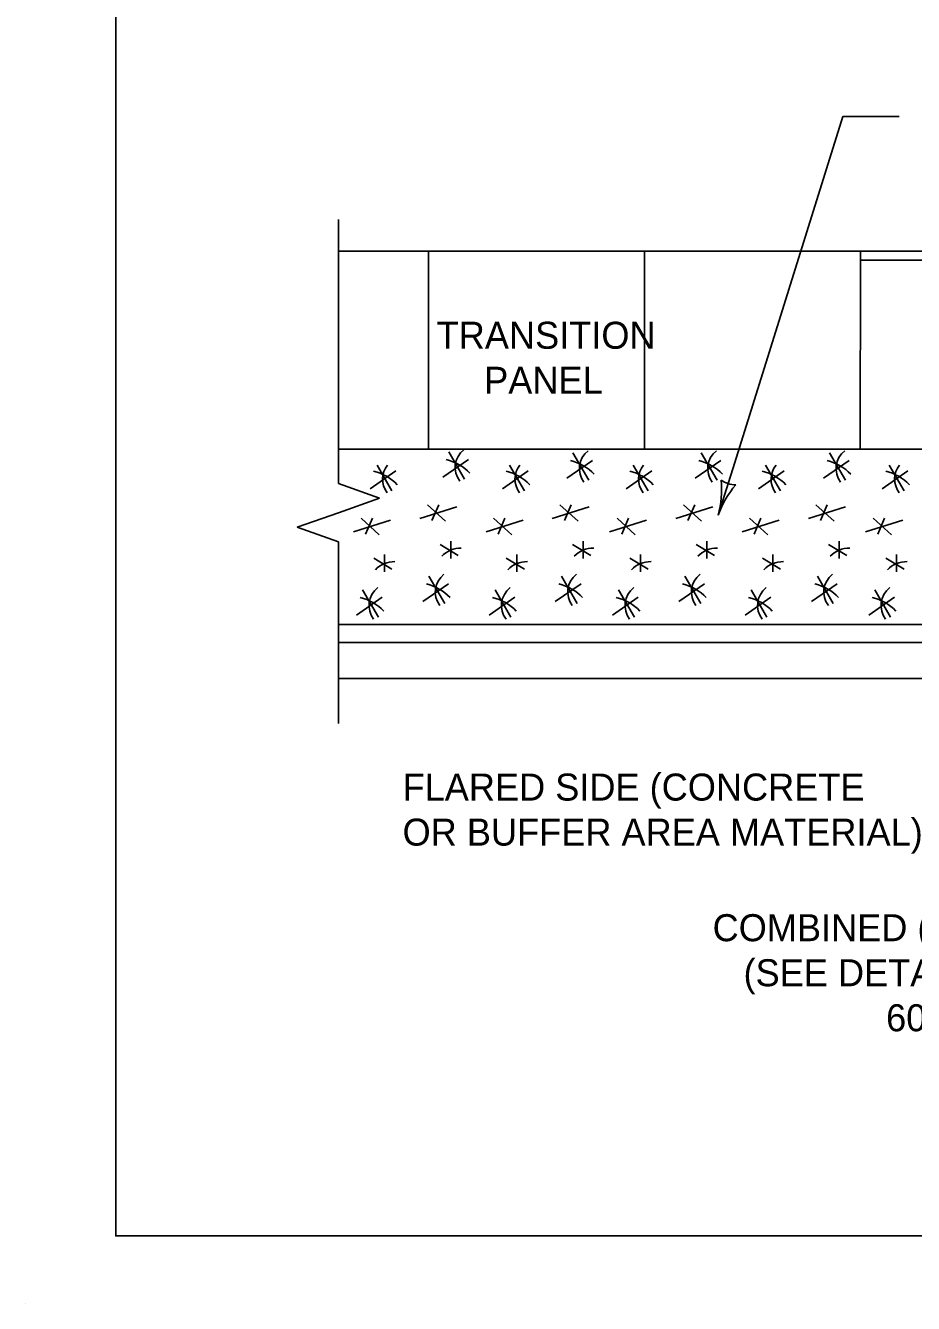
# Model space of a CAD drawing. Extents: x 49991.4 to 50021, y 49987.6 to 50011.4.
# Drawn here: x 50009.537 to 50011.508, y 49999.736 to 50002.573 of the extents above; entities that cross this region are included whole.
import ezdxf

# ---------------------------------------------------------------- set-up
doc = ezdxf.new("R2010")
doc.units = 0
for name, color, linetype in [('Level 1', 7, 'Continuous'), ('Level 2', 7, 'Continuous'), ('Level 3', 7, 'Continuous'), ('Level 6', 7, 'Continuous')]:
    doc.layers.add(name, color=color, linetype=linetype)

msp = doc.modelspace()

# ---------------------------------------------------------------- linework, layer by layer
at = {"layer": 'Level 1'}
for p, q in [((50010.2316, 50002.0716), (50014.16, 50002.0715)), ((50010.4316, 50002.0716), (50010.4317, 50001.6322)), ((50010.911, 50002.0716), (50010.9109, 50001.6323)), ((50011.3901, 50002.0715), (50011.3899, 50001.6323)), ((50011.3901, 50002.0515), (50013.0671, 50002.0516)), ((50010.2317, 50001.6321), (50014.16, 50001.6325)), ((50010.4895, 50001.6321), (50010.4895, 50001.6322)), ((50010.7728, 50001.6322), (50010.7729, 50001.6321)), ((50010.7835, 50001.6321), (50010.7835, 50001.6322)), ((50011.0471, 50001.6322), (50011.0472, 50001.6321)), ((50011.0578, 50001.6321), (50011.0579, 50001.6322)), ((50011.3411, 50001.6322), (50011.3412, 50001.6321)), ((50011.3518, 50001.6321), (50011.3519, 50001.6322)), ((50010.4632, 50001.57), (50010.5203, 50001.6096)), ((50010.4766, 50001.6264), (50010.5118, 50001.5654)), ((50010.7388, 50001.5677), (50010.7959, 50001.6073)), ((50010.7522, 50001.6241), (50010.7875, 50001.5631)), ((50011.0236, 50001.5677), (50011.0807, 50001.6073)), ((50011.037, 50001.6241), (50011.0723, 50001.5631)), ((50011.3084, 50001.5677), (50011.3655, 50001.6073)), ((50011.3218, 50001.6241), (50011.3571, 50001.5631)), ((50010.302, 50001.5443), (50010.359, 50001.5839)), ((50010.3175, 50001.5969), (50010.3506, 50001.5396)), ((50010.596, 50001.5443), (50010.653, 50001.5839)), ((50010.6115, 50001.5969), (50010.6446, 50001.5396)), ((50010.8703, 50001.5443), (50010.9273, 50001.5839)), ((50010.8858, 50001.5969), (50010.9189, 50001.5396)), ((50011.1643, 50001.5443), (50011.2213, 50001.5839)), ((50011.1798, 50001.5969), (50011.2129, 50001.5396)), ((50011.4386, 50001.5443), (50011.4957, 50001.5839)), ((50011.4541, 50001.5969), (50011.4872, 50001.5396)), ((50010.4124, 50001.4783), (50010.4946, 50001.5043)), ((50010.4695, 50001.4722), (50010.4291, 50001.5088)), ((50010.4393, 50001.4738), (50010.4544, 50001.5088)), ((50010.7064, 50001.4783), (50010.7886, 50001.5043)), ((50010.7635, 50001.4722), (50010.7231, 50001.5088)), ((50010.7333, 50001.4738), (50010.7484, 50001.5088)), ((50010.9807, 50001.4783), (50011.0629, 50001.5043)), ((50011.0378, 50001.4722), (50010.9974, 50001.5088)), ((50011.0076, 50001.4738), (50011.0227, 50001.5088)), ((50011.2747, 50001.4783), (50011.3569, 50001.5043)), ((50011.3318, 50001.4722), (50011.2914, 50001.5088)), ((50011.3016, 50001.4738), (50011.3167, 50001.5088)), ((50010.2653, 50001.4483), (50010.3475, 50001.4743)), ((50010.3223, 50001.4422), (50010.282, 50001.4788)), ((50010.2921, 50001.4438), (50010.3072, 50001.4788)), ((50010.5593, 50001.4483), (50010.6415, 50001.4743)), ((50010.6163, 50001.4422), (50010.576, 50001.4788)), ((50010.5861, 50001.4438), (50010.6012, 50001.4788)), ((50010.8336, 50001.4483), (50010.9158, 50001.4743)), ((50010.8907, 50001.4422), (50010.8503, 50001.4788)), ((50010.8605, 50001.4438), (50010.8756, 50001.4788)), ((50011.1276, 50001.4483), (50011.2098, 50001.4743)), ((50011.1847, 50001.4422), (50011.1443, 50001.4788)), ((50011.1545, 50001.4438), (50011.1696, 50001.4788)), ((50011.4019, 50001.4483), (50011.4841, 50001.4743)), ((50011.459, 50001.4422), (50011.4186, 50001.4788)), ((50011.4288, 50001.4438), (50011.4439, 50001.4788)), ((50010.4575, 50001.4203), (50010.4977, 50001.3959)), ((50010.4809, 50001.3898), (50010.4809, 50001.428)), ((50010.7515, 50001.4203), (50010.7917, 50001.3959)), ((50010.7749, 50001.3898), (50010.7749, 50001.428)), ((50011.0258, 50001.4203), (50011.0661, 50001.3959)), ((50011.0492, 50001.3898), (50011.0492, 50001.428)), ((50011.3198, 50001.4203), (50011.3601, 50001.3959)), ((50011.3432, 50001.3898), (50011.3432, 50001.428)), ((50010.3104, 50001.3903), (50010.3506, 50001.3659)), ((50010.3338, 50001.3598), (50010.3338, 50001.398)), ((50010.6044, 50001.3903), (50010.6446, 50001.3659)), ((50010.6278, 50001.3598), (50010.6278, 50001.398)), ((50010.8787, 50001.3903), (50010.9189, 50001.3659)), ((50010.9021, 50001.3598), (50010.9021, 50001.398)), ((50011.1727, 50001.3903), (50011.2129, 50001.3659)), ((50011.1961, 50001.3598), (50011.1961, 50001.398)), ((50011.447, 50001.3903), (50011.4872, 50001.3659)), ((50011.4704, 50001.3598), (50011.4704, 50001.398)), ((50010.4325, 50001.3501), (50010.4677, 50001.2892)), ((50010.7265, 50001.3501), (50010.7617, 50001.2892)), ((50011.0008, 50001.3501), (50011.0361, 50001.2892)), ((50011.2948, 50001.3501), (50011.3301, 50001.2892)), ((50010.2853, 50001.3201), (50010.3206, 50001.2592)), ((50010.4191, 50001.2938), (50010.4762, 50001.3334)), ((50010.5793, 50001.3201), (50010.6146, 50001.2592)), ((50010.7131, 50001.2938), (50010.7702, 50001.3334)), ((50010.8537, 50001.3201), (50010.8889, 50001.2592)), ((50010.9874, 50001.2938), (50011.0445, 50001.3334)), ((50011.1477, 50001.3201), (50011.1829, 50001.2592)), ((50011.2814, 50001.2938), (50011.3385, 50001.3334)), ((50011.422, 50001.3201), (50011.4572, 50001.2592)), ((50010.272, 50001.2638), (50010.329, 50001.3034)), ((50010.566, 50001.2638), (50010.623, 50001.3034)), ((50010.8403, 50001.2638), (50010.8973, 50001.3034)), ((50011.1343, 50001.2638), (50011.1913, 50001.3034)), ((50011.4086, 50001.2638), (50011.4657, 50001.3034)), ((50010.2316, 50001.243), (50014.16, 50001.2435)), ((50010.2316, 50001.2033), (50014.16, 50001.2029)), ((50010.2316, 50001.1232), (50014.16, 50001.1232)), ((50009.5374, 49999.7356), (50009.5374, 49999.7356)), ((50009.5374, 49999.7356), (50009.5374, 49999.7356))]:
    msp.add_line(p, q, dxfattribs=at)
msp.add_lwpolyline([(50020.9378, 50008.1646), (50009.7374, 50008.1646), (50009.7374, 49999.8856), (50020.9378, 49999.8856)], close=True, dxfattribs=at)
msp.add_lwpolyline([(50020.9378, 50008.1646), (50009.7374, 50008.1646), (50009.7374, 49999.8856), (50020.9378, 49999.8856)], close=True, dxfattribs=at)
for centre, major_axis, start_param, end_param in [((50010.4284, 50001.5492), (0.1074, 0), 1.015046, 1.015484), ((50010.6827, 50001.5955), (-0.0591, 0), 5.529887, 5.530814), ((50010.8298, 50001.6255), (-0.0591, 0), 6.157329, 6.158231), ((50010.7224, 50001.5492), (0.1074, 0), 1.015046, 1.015994), ((50010.957, 50001.5955), (-0.0591, 0), 5.529262, 5.530814), ((50011.1041, 50001.6255), (-0.0591, 0), 6.15687, 6.158231), ((50010.9968, 50001.5492), (0.1074, 0), 1.015046, 1.016469), ((50011.251, 50001.5955), (-0.0591, 0), 5.528592, 5.530814), ((50011.3981, 50001.6255), (-0.0591, 0), 6.156378, 6.158231), ((50011.2908, 50001.5492), (0.1074, 0), 1.015046, 1.016979), ((50011.5253, 50001.5955), (-0.0591, 0), 5.527967, 5.530814), ((50010.4425, 50001.5151), (0.1074, 0), 0.715682, 1.301104), ((50010.5499, 50001.5913), (-0.0591, 0), 5.450961, 6.875887), ((50010.7182, 50001.5128), (0.1074, 0), 0.715682, 1.301104), ((50010.8255, 50001.589), (-0.0591, 0), 5.450961, 6.875887), ((50011.003, 50001.5128), (0.1074, 0), 0.715682, 1.301104), ((50011.1103, 50001.589), (-0.0591, 0), 5.450961, 6.875887), ((50011.2878, 50001.5128), (0.1074, 0), 0.715682, 1.301104), ((50011.3952, 50001.589), (-0.0591, 0), 5.450961, 6.875887), ((50010.2813, 50001.4893), (0.1074, 0), 0.715682, 1.301104), ((50010.3887, 50001.5656), (-0.0591, 0), 5.660038, 6.875887), ((50010.5753, 50001.4893), (0.1074, 0), 0.715682, 1.301104), ((50010.6827, 50001.5656), (-0.0591, 0), 5.660038, 6.875887), ((50010.8496, 50001.4893), (0.1074, 0), 0.715682, 1.301104), ((50010.957, 50001.5656), (-0.0591, 0), 5.660038, 6.875887), ((50011.1436, 50001.4893), (0.1074, 0), 0.715682, 1.301104), ((50011.251, 50001.5656), (-0.0591, 0), 5.660038, 6.875887), ((50011.418, 50001.4893), (0.1074, 0), 0.715682, 1.301104), ((50011.5253, 50001.5656), (-0.0591, 0), 5.660038, 6.875887), ((50010.5045, 50001.3606), (-0.0573, 0), 4.712389, 5.577205), ((50010.7985, 50001.3606), (-0.0573, 0), 4.712389, 5.577205), ((50011.0728, 50001.3606), (-0.0573, 0), 4.712389, 5.577205), ((50011.3668, 50001.3606), (-0.0573, 0), 4.712389, 5.577205), ((50010.3573, 50001.3306), (-0.0573, 0), 4.712389, 5.577205), ((50010.6513, 50001.3306), (-0.0573, 0), 4.712389, 5.577205), ((50010.9257, 50001.3306), (-0.0573, 0), 4.712389, 5.577205), ((50011.2197, 50001.3306), (-0.0573, 0), 4.712389, 5.577205), ((50011.494, 50001.3306), (-0.0573, 0), 4.712389, 5.577205), ((50010.5058, 50001.3151), (-0.0591, 0), 5.450961, 6.875887), ((50010.7998, 50001.3151), (-0.0591, 0), 5.450961, 6.875887), ((50011.0741, 50001.3151), (-0.0591, 0), 5.450961, 6.875887), ((50011.3681, 50001.3151), (-0.0591, 0), 5.450961, 6.875887), ((50010.3587, 50001.2851), (-0.0591, 0), 5.450961, 6.875887), ((50010.3984, 50001.2388), (0.1074, 0), 0.715682, 1.301104), ((50010.6527, 50001.2851), (-0.0591, 0), 5.450961, 6.875887), ((50010.6924, 50001.2388), (0.1074, 0), 0.715682, 1.301104), ((50010.927, 50001.2851), (-0.0591, 0), 5.450961, 6.875887), ((50010.9668, 50001.2388), (0.1074, 0), 0.715682, 1.301104), ((50011.221, 50001.2851), (-0.0591, 0), 5.450961, 6.875887), ((50011.2608, 50001.2388), (0.1074, 0), 0.715682, 1.301104), ((50011.4953, 50001.2851), (-0.0591, 0), 5.450961, 6.875887), ((50010.2513, 50001.2088), (0.1074, 0), 0.715682, 1.301104), ((50010.5453, 50001.2088), (0.1074, 0), 0.715682, 1.301104), ((50010.8196, 50001.2088), (0.1074, 0), 0.715682, 1.301104), ((50011.1136, 50001.2088), (0.1074, 0), 0.715682, 1.301104), ((50011.388, 50001.2088), (0.1074, 0), 0.715682, 1.301104)]:
    msp.add_ellipse(centre, major_axis=major_axis, ratio=0.909091, start_param=start_param, end_param=end_param, dxfattribs=at)
at = {"layer": 'Level 3'}
for p, q in [((50011.1112, 50001.6023), (50011.3511, 50002.3706)), ((50011.3511, 50002.3706), (50011.4765, 50002.3706)), ((50011.0748, 50001.4856), (50011.1112, 50001.6023))]:
    msp.add_line(p, q, dxfattribs=at)
for centre, radius, start, end in [((50010.8493, 50001.544), 0.233, 345.4909, 4.7408), ((50011.2841, 50001.4107), 0.2223, 140.1196, 160.3031), ((50011.113, 50001.608), 0.0548, 234.8024, 270.5248)]:
    msp.add_arc(centre, radius, start, end, dxfattribs=at)
at = {"layer": 'Level 6'}
for p, q in [((50010.2316, 50002.1417), (50010.2316, 50001.5559)), ((50010.2316, 50001.5559), (50010.323, 50001.5235)), ((50010.323, 50001.5235), (50010.2316, 50001.4911)), ((50010.2316, 50001.4911), (50010.1402, 50001.4587)), ((50010.1402, 50001.4587), (50010.2316, 50001.4263)), ((50010.2316, 50001.4263), (50010.2316, 50001.0232))]:
    msp.add_line(p, q, dxfattribs=at)

# ---------------------------------------------------------------- texts
at = {"layer": 'Level 2'}
for s, p in [('TRANSITION', (50010.4498, 50001.8551)), ('PANEL ', (50010.5552, 50001.7551)), ('FLARED SIDE (CONCRETE', (50010.3741, 50000.852)), ('OR BUFFER AREA MATERIAL)', (50010.3741, 50000.752)), ('COMBINED (PARALLEL/PERPENDICULAR) CURB RAMP', (50011.0622, 50000.5398)), ('(SEE DETAILED DRAWING NUMBERS 608-25 AND', (50011.1309, 50000.4398)), ('608-30 FOR ADDITIONAL DETAILS)', (50011.4473, 50000.3398))]:
    msp.add_text(s, height=0.06, dxfattribs=at).set_placement(p)

doc.saveas('drawing.dxf')
